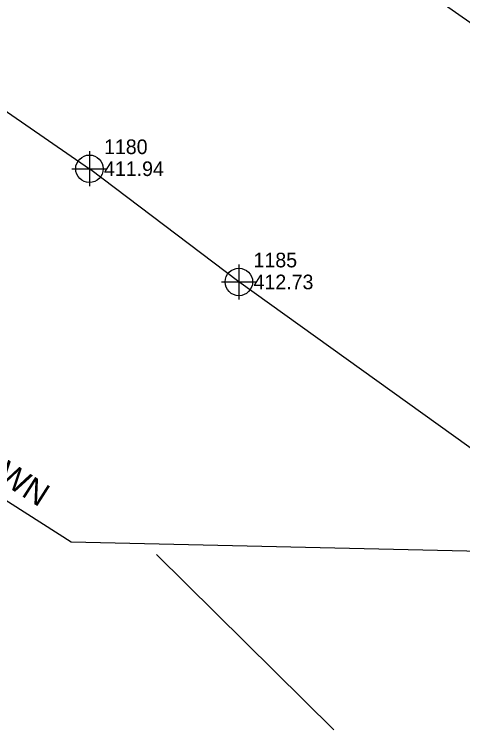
# Model space of a CAD drawing. Extents: x 2024146 to 2025516, y 819906 to 820765.
# Drawn here: x 2025059.4 to 2025136, y 820045.6 to 820167.9 of the extents above; entities that cross this region are included whole.
import ezdxf

# ---------------------------------------------------------------- set-up
doc = ezdxf.new("R2010")
doc.units = 0
for name, color, linetype in [('Prop DSN Text', 7, 'Continuous'), ('Prop Lane Lines', 7, 'Continuous'), ('Prop Superelevation  Arrow CELL', 7, 'Continuous'), ('Sheet Block Revision CELL', 7, 'Continuous'), ('Sheet Layout Plan Border', 7, 'Continuous'), ('Sheet Layout Profile Border Port 2', 7, 'Continuous'), ('Sheet Plan And Profile CELL', 7, 'Continuous')]:
    doc.layers.add(name, color=color, linetype=linetype)

msp = doc.modelspace()

# ---------------------------------------------------------------- linework, layer by layer
at = {"layer": 'Prop Lane Lines'}
msp.add_lwpolyline([(2024566.33, 820397.9), (2024753.12, 820279.6), (2025069.15, 820077.77), (2025141.71, 820076.11)], dxfattribs=at)
at = {"layer": 'Prop Superelevation  Arrow CELL'}
msp.add_lwpolyline([(2025083.7, 820075.56), (2025113.98, 820045.65)], dxfattribs=at)
at = {"layer": 'Sheet Layout Plan Border'}
for points in [[(2025072.24, 820144.49), (2025072.24, 820141.49)], [(2025069.24, 820141.49), (2025072.24, 820141.49)], [(2025072.24, 820141.49), (2025075.24, 820141.49)], [(2025072.24, 820141.49), (2025072.24, 820138.49)], [(2025097.78, 820125.14), (2025097.78, 820122.14)], [(2025094.78, 820122.14), (2025097.78, 820122.14)], [(2025097.78, 820122.14), (2025100.78, 820122.14)], [(2025097.78, 820122.14), (2025097.78, 820119.14)]]:
    msp.add_lwpolyline(points, dxfattribs=at)
for centre in [(2025072.24, 820141.49), (2025097.78, 820122.14)]:
    msp.add_circle(centre, 2.34, dxfattribs=at)
at = {"layer": 'Sheet Plan And Profile CELL'}
for points in [[(2024826.71, 820365.84), (2024835.33, 820357.93), (2024866.41, 820337.18), (2024892.38, 820321.46), (2024924.16, 820301.03), (2024946.59, 820287.22), (2024967.06, 820274.36), (2024988.57, 820261.62), (2025010.79, 820248.47), (2025045.82, 820229.11), (2025063.46, 820215.95), (2025102.86, 820187.61), (2025131, 820170.89), (2025157.73, 820152.25), (2025180.55, 820137.37)], [(2025034.06, 820167.86), (2025072.24, 820141.49)], [(2025097.78, 820122.14), (2025072.24, 820141.49)], [(2025142.26, 820090.2), (2025097.78, 820122.14)]]:
    msp.add_lwpolyline(points, dxfattribs=at)

# ---------------------------------------------------------------- texts
at = {"layer": 'Prop DSN Text'}
msp.add_text('24" TYPE UNKNOWN', height=4, rotation=327.4366, dxfattribs=at).set_placement((2025019.03, 820112.15))
at = {"layer": 'Sheet Block Revision CELL'}
for s, p in [('1180', (2025074.74, 820143.99)), ('1185', (2025100.28, 820124.64))]:
    msp.add_text(s, height=2.5, dxfattribs=at).set_placement(p)
at = {"layer": 'Sheet Layout Profile Border Port 2'}
for s, p in [('411.94', (2025074.74, 820140.24)), ('412.73', (2025100.28, 820120.89))]:
    msp.add_text(s, height=2.5, dxfattribs=at).set_placement(p)

doc.saveas('drawing.dxf')
